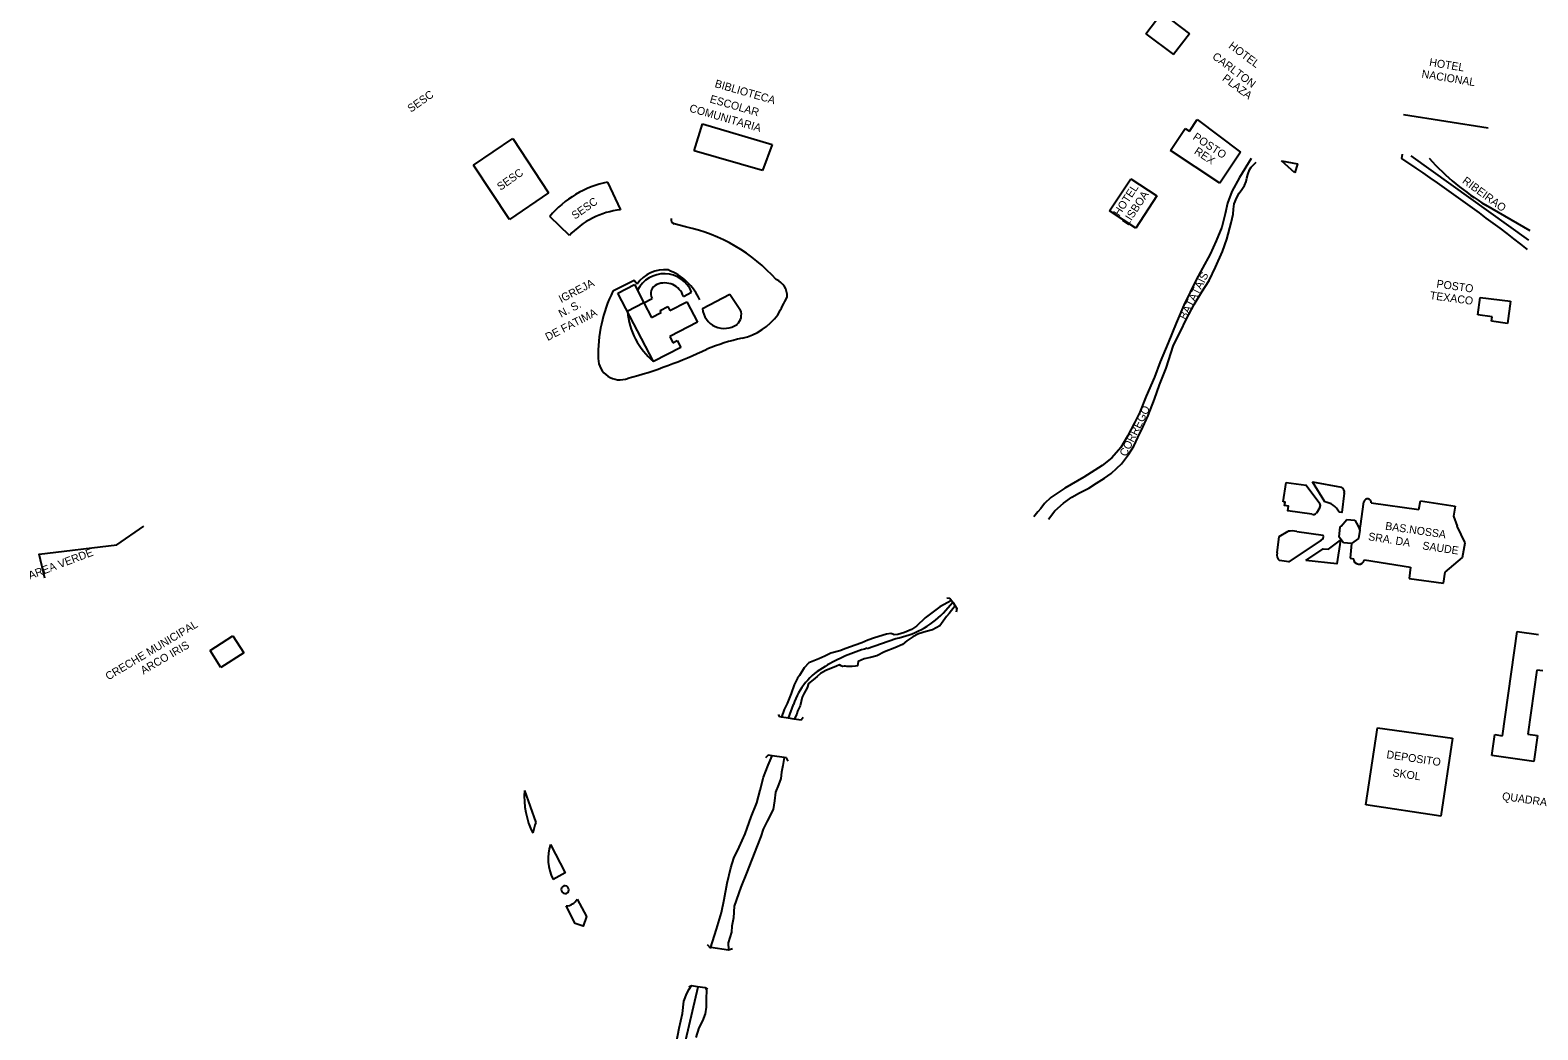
# Model space of a CAD drawing. Extents: x 325899 to 363134, y 7578590 to 7592502.
# Drawn here: x 337530 to 338292, y 7589247 to 7589753 of the extents above; entities that cross this region are included whole.
import ezdxf

# ---------------------------------------------------------------- set-up
doc = ezdxf.new("R2010")
doc.units = 0
for name, color, linetype in [('EDIFEXISTENT', 7, 'Continuous'), ('EDIFIDENTIF', 7, 'Continuous'), ('EDIFOBRAEXIS', 7, 'Continuous')]:
    doc.layers.add(name, color=color, linetype=linetype)

msp = doc.modelspace()

# ---------------------------------------------------------------- linework, layer by layer
at = {"layer": 'EDIFEXISTENT'}
for p, q in [((338093.53, 7589750.59), (338101.54, 7589761.3)), ((338101.54, 7589761.3), (338115.64, 7589750.75)), ((338093.53, 7589750.59), (338107.46, 7589740.16)), ((338115.64, 7589750.75), (338107.46, 7589740.16)), ((337865.22, 7589691.61), (337869.48, 7589705.19)), ((337869.48, 7589705.19), (337904.68, 7589694.73)), ((338105.97, 7589691.77), (338113.33, 7589702.92)), ((338113.33, 7589702.92), (338115.51, 7589701.48)), ((338115.51, 7589701.48), (338119.4, 7589707.4)), ((338119.4, 7589707.4), (338141.3, 7589690.91)), ((338223.69, 7589709.95), (338266.52, 7589703.2)), ((337753.58, 7589684.27), (337773.5, 7589697.83)), ((337773.5, 7589697.83), (337791.63, 7589670.29)), ((337899.77, 7589681.63), (337865.22, 7589691.61)), ((337904.68, 7589694.73), (337899.77, 7589681.63)), ((338130.96, 7589675.27), (338105.97, 7589691.77)), ((338141.3, 7589690.91), (338130.96, 7589675.27)), ((337771.86, 7589656.78), (337753.58, 7589684.27)), ((337821.38, 7589675.69), (337828.01, 7589661.75)), ((338075.18, 7589661.24), (338085.91, 7589677.48)), ((338085.91, 7589677.48), (338099.14, 7589668.74)), ((337791.63, 7589670.29), (337771.86, 7589656.78)), ((338099.14, 7589668.74), (338088.41, 7589652.48)), ((337802.14, 7589648.71), (337792.16, 7589658.35)), ((338088.41, 7589652.48), (338075.18, 7589661.24)), ((337826.65, 7589619.68), (337834.98, 7589624.01)), ((337844.63, 7589585.05), (337826.65, 7589619.68)), ((337834.98, 7589624.01), (337839.78, 7589614.76)), ((337859.74, 7589618.02), (337863.92, 7589620.19)), ((337839.78, 7589614.76), (337831.4, 7589610.41)), ((337839.78, 7589614.76), (337843.97, 7589616.93)), ((337839.78, 7589614.76), (337843.6, 7589607.39)), ((337847.94, 7589610.89), (337851.92, 7589612.96)), ((337851.92, 7589612.96), (337852.96, 7589610.95)), ((337852.96, 7589610.95), (337861.4, 7589615.33)), ((337861.4, 7589615.33), (337866.79, 7589604.93)), ((338261.32, 7589608.77), (338262.58, 7589617.5)), ((338262.58, 7589617.5), (338277.81, 7589615.53)), ((338277.81, 7589615.53), (338276.29, 7589604.36)), ((337843.6, 7589607.39), (337848.45, 7589609.91)), ((337848.45, 7589609.91), (337847.94, 7589610.89)), ((337866.79, 7589604.93), (337852.81, 7589597.68)), ((338268.55, 7589607.71), (338261.32, 7589608.77)), ((338268.2, 7589605.42), (338268.55, 7589607.71)), ((338276.29, 7589604.36), (338268.2, 7589605.42)), ((337852.81, 7589597.68), (337854.46, 7589594.51)), ((337858.46, 7589592.17), (337844.63, 7589585.05)), ((337854.46, 7589594.51), (337856.65, 7589595.65)), ((337856.65, 7589595.65), (337858.46, 7589592.17)), ((338202.06, 7589501.91), (338203.77, 7589514.19)), ((338207.48, 7589513.69), (338231.55, 7589510.41)), ((338231.55, 7589510.41), (338232.29, 7589514.74)), ((338232.29, 7589514.74), (338249.9, 7589512)), ((338249.9, 7589512), (338249.05, 7589507.02)), ((338192.22, 7589501.91), (338195.19, 7589505.25)), ((338195.19, 7589505.25), (338199.08, 7589504.94)), ((338199.08, 7589504.94), (338200.78, 7589501.91)), ((338249.05, 7589507.02), (338250.95, 7589501.91)), ((338191.18, 7589496.4), (338191.81, 7589501.57)), ((338191.81, 7589501.57), (338192.22, 7589501.91)), ((338200.78, 7589501.91), (338201.7, 7589499.84)), ((338201.7, 7589499.84), (338200.96, 7589495.74)), ((338201.7, 7589499.84), (338202.06, 7589501.91)), ((338254.87, 7589493.5), (338250.95, 7589501.91)), ((338193.38, 7589493.5), (338191.18, 7589496.4)), ((338197.46, 7589493.16), (338193.38, 7589493.5)), ((338197.46, 7589493.16), (338196.77, 7589485.81)), ((338200.96, 7589495.74), (338197.46, 7589493.16)), ((338253.54, 7589486.01), (338254.87, 7589493.5)), ((338196.77, 7589485.81), (338198.49, 7589485.46)), ((338203.99, 7589484.83), (338227.31, 7589481.19)), ((338244.86, 7589478.68), (338253.54, 7589486.01)), ((338227.31, 7589481.19), (338226.67, 7589475.44)), ((338226.67, 7589475.44), (338243.95, 7589473.06)), ((338243.95, 7589473.06), (338244.86, 7589478.68)), ((337992.92, 7589465.74), (337994.44, 7589465.6)), ((337994.44, 7589465.6), (337995.31, 7589464.32)), ((337995.31, 7589464.32), (337995.88, 7589463.48)), ((337995.88, 7589463.48), (337997.09, 7589461.71)), ((337997.09, 7589461.71), (337998.02, 7589460.35)), ((337998.02, 7589460.35), (337997.57, 7589458.45)), ((337620.49, 7589439.11), (337631.95, 7589446.45)), ((337631.95, 7589446.45), (337637.48, 7589437.98)), ((338273.74, 7589396.03), (338281.22, 7589448.72)), ((338281.22, 7589448.72), (338292.01, 7589447.19)), ((337625.91, 7589430.44), (337620.49, 7589439.11)), ((337637.48, 7589437.98), (337625.91, 7589430.44)), ((338291.22, 7589429.21), (338286.62, 7589396.85)), ((338294.24, 7589428.78), (338291.22, 7589429.21)), ((337908.46, 7589405.55), (337907.75, 7589406.8)), ((337909.31, 7589405.42), (337908.46, 7589405.55)), ((337912.85, 7589404.89), (337909.31, 7589405.42)), ((337915.76, 7589404.46), (337912.85, 7589404.89)), ((337919.22, 7589403.94), (337915.76, 7589404.46)), ((337920.34, 7589405.15), (337919.22, 7589403.94)), ((338204.77, 7589361.02), (338210.56, 7589400.04)), ((338210.56, 7589400.04), (338248.45, 7589394.82)), ((338248.45, 7589394.82), (338242.6, 7589355.41)), ((338268.41, 7589386.08), (338269.9, 7589396.57)), ((338269.9, 7589396.57), (338273.74, 7589396.03)), ((338286.62, 7589396.85), (338291.55, 7589396.15)), ((338291.55, 7589396.15), (338289.69, 7589383.06)), ((337902.54, 7589386.21), (337901.18, 7589384.93)), ((337904.64, 7589385.88), (337902.54, 7589386.21)), ((337910.6, 7589384.97), (337904.64, 7589385.88)), ((337911.8, 7589384.79), (337910.6, 7589384.97)), ((337912.73, 7589383.23), (337911.8, 7589384.79)), ((338289.69, 7589383.06), (338268.41, 7589386.08)), ((338242.6, 7589355.41), (338204.77, 7589361.02)), ((337871.8, 7589290.58), (337873.48, 7589288.61)), ((337873.48, 7589288.61), (337873.56, 7589289.19)), ((337873.56, 7589289.19), (337882.59, 7589287.87)), ((337882.59, 7589287.87), (337884.59, 7589288.54)), ((337862.51, 7589269.18), (337863.79, 7589269.85)), ((337863.79, 7589269.85), (337866.83, 7589269.35)), ((337866.83, 7589269.35), (337870.78, 7589268.81)), ((337870.78, 7589268.81), (337871.88, 7589267.93))]:
    msp.add_line(p, q, dxfattribs=at)
for centre, radius, start, end in [((337831.24, 7589625.78), 50.87, 101.1753, 140.19577), ((337832.18, 7589621.28), 40.68, 95.88187, 137.60579), ((337849.99, 7589614.35), 15.09, 22.73511, 152.90651), ((337848.02, 7589619.5), 4.79, 110.21393, 212.35293), ((337850.32, 7589614.89), 9.93, 18.37494, 113.51914), ((338205.61, 7589513.82), 1.88, 356.15001, 168.63769), ((338201.27, 7589485.46), 2.78, 179.8605, 347.06276)]:
    msp.add_arc(centre, radius, start, end, dxfattribs=at)
at = {"layer": 'EDIFOBRAEXIS'}
for points in [[(338146.68, 7589687.63), (338140.82, 7589678.11), (338137.03, 7589671.01), (338134.8, 7589665.04), (338133.54, 7589659.72), (338131.88, 7589653.01), (338129.04, 7589646.04), (338126.03, 7589639.38), (338122.18, 7589632.23), (338118.99, 7589626.32), (338112.74, 7589613.6), (338108.89, 7589604.47), (338104.77, 7589594.5), (338100.82, 7589584.94), (338097.81, 7589577.13), (338093.69, 7589567.64), (338090.55, 7589559.48), (338087.69, 7589554.18), (338084.25, 7589547.32), (338080.83, 7589541.62), (338076.39, 7589536.45), (338071.47, 7589532.58), (338062.2, 7589526.64), (338052.58, 7589521.03), (338045.42, 7589516.46), (338042.2, 7589513.38), (338040.38, 7589510.81), (338038.88, 7589509.08), (338036.83, 7589506.61)], [(338230.1, 7589682.84), (338222.94, 7589687.69), (338223.28, 7589689.81)], [(338287.12, 7589646.39), (338227.63, 7589689.08)], [(338044.3, 7589505.45), (338047.52, 7589509.71), (338051.88, 7589513.48), (338056.15, 7589516.51), (338060.01, 7589518.68), (338064.68, 7589521.15), (338068.51, 7589523.7), (338072.6, 7589526.15), (338076.02, 7589528.57), (338078.89, 7589531.17), (338081.25, 7589533.46), (338084.72, 7589538.04), (338087.46, 7589542.34), (338089.38, 7589546.69), (338091.94, 7589551.98), (338094.6, 7589557.83), (338097.94, 7589566.07), (338100.34, 7589573.37), (338103.78, 7589581.77), (338107.47, 7589593.34), (338111.04, 7589600.26), (338113.9, 7589606.39), (338117.9, 7589613.89), (338121.82, 7589620.26), (338125.45, 7589625.96), (338128.69, 7589632.8), (338132.26, 7589640.66), (338134.45, 7589646.97), (338136.57, 7589655.18), (338137.61, 7589659.48), (338137.78, 7589662.15), (338138.21, 7589664.74), (338139.42, 7589668.02), (338140.66, 7589670.21), (338141.95, 7589672.07), (338143.37, 7589674.05), (338144.16, 7589676.04), (338144.54, 7589677.76), (338144.99, 7589679.65), (338145.9, 7589681.96), (338146.76, 7589683.36), (338149.32, 7589685.88)], [(338162.09, 7589686.45), (338170.21, 7589684.98), (338168.77, 7589680.42)], [(338168.77, 7589680.42), (338162.09, 7589686.45)], [(338287.74, 7589651.18), (338265.42, 7589664.14)], [(337860.89, 7589653.12), (337855.01, 7589654.71)], [(337836.34, 7589624.22), (337834.89, 7589626.07), (337824.09, 7589620.61)], [(337869.39, 7589611.91), (337883.17, 7589619.21)], [(337883.17, 7589619.21), (337888.63, 7589611.08)], [(338162.86, 7589514.2), (338164.46, 7589523.94)], [(338164.46, 7589523.94), (338174.53, 7589522.7), (338181.47, 7589513.42)], [(338183.94, 7589514.12), (338177.73, 7589524.24)], [(338177.73, 7589524.24), (338192.46, 7589521.57)], [(338177.43, 7589508.02), (338165.27, 7589509.73), (338165.59, 7589511.97), (338163.68, 7589512.4), (338163.9, 7589514.05), (338162.86, 7589514.2)], [(338193.76, 7589518.5), (338192.55, 7589508.86), (338191.15, 7589509.01)], [(338181.38, 7589511.31), (338179.74, 7589508.43)], [(337536.87, 7589475.67), (337534.16, 7589487.82), (337573.38, 7589492.49), (337587.02, 7589501.91)], [(338159.87, 7589488.41), (338160.93, 7589496.64)], [(338160.93, 7589496.64), (338165.39, 7589499.36)], [(338169.78, 7589499.27), (338183.17, 7589497.31)], [(338182.19, 7589494.86), (338165.74, 7589483.89), (338161.11, 7589484.52)], [(338174.32, 7589484.5), (338183.14, 7589490.46), (338185.9, 7589490.31), (338191.85, 7589494.75), (338190.07, 7589482.8), (338174.32, 7589484.5)], [(337995.31, 7589464.32), (337989.35, 7589461.18), (337981.98, 7589455.54), (337977.63, 7589451.44), (337975.06, 7589449.64), (337971.44, 7589448.2), (337968.19, 7589447.24), (337966.21, 7589447.03), (337965.68, 7589447.41), (337964.54, 7589447.75), (337962.33, 7589447.36), (337956.33, 7589445.49), (337952.9, 7589444.35), (337949.9, 7589442.96), (337946.57, 7589441.79), (337941.81, 7589440.16), (337938.76, 7589438.97), (337934.23, 7589437.66), (337931.26, 7589436.24), (337928.13, 7589434.95), (337923.14, 7589432.92), (337920.83, 7589430.25), (337918.49, 7589426.39), (337917.37, 7589425.18), (337915.82, 7589421.67), (337914.26, 7589417.3), (337912.16, 7589412.22), (337910.74, 7589409.26), (337909.31, 7589405.42)], [(337997.09, 7589461.71), (337994.07, 7589457.74), (337992.79, 7589456.21), (337991.07, 7589453.89), (337989.4, 7589451.62), (337985.68, 7589449.5), (337982.53, 7589448.61), (337978.61, 7589447.56), (337975.66, 7589445.98), (337972.65, 7589443.98), (337970.45, 7589442.05), (337966.61, 7589440.38), (337961.45, 7589438.42), (337957.5, 7589436.35), (337954.4, 7589435.59), (337951.17, 7589434.83), (337948.17, 7589433.49), (337947.69, 7589431.36), (337946.7, 7589431.09), (337945.08, 7589431.03), (337943.61, 7589431.04), (337942.29, 7589431), (337941.61, 7589431.21), (337941.05, 7589431.09), (337940.13, 7589430.92), (337939.53, 7589431.31), (337938.7, 7589431.85), (337937.2, 7589431.1), (337931.8, 7589429.04), (337929.13, 7589427.44), (337927.36, 7589425.86), (337925.27, 7589424.23), (337923, 7589422.37), (337922.27, 7589420.25), (337920.8, 7589417.6), (337919.77, 7589415.58), (337918.77, 7589411.15), (337917.38, 7589408.47), (337917.16, 7589406.93), (337915.76, 7589404.46)], [(337991.05, 7589457.9), (337995.88, 7589463.48)], [(337952.61, 7589440.17), (337967.13, 7589445.22)], [(337912.85, 7589404.89), (337915.35, 7589411.84)], [(337873.48, 7589288.61), (337876.48, 7589298.22), (337879.06, 7589306.62), (337880.33, 7589313.25), (337881.95, 7589321.55), (337883.72, 7589329.35), (337885.25, 7589334.15), (337887.99, 7589339.76), (337890.91, 7589346.5), (337894.05, 7589355.07), (337896.85, 7589362.12), (337898.55, 7589368.49), (337900.31, 7589375.1), (337902.67, 7589381.06), (337904.64, 7589385.88)], [(337910.6, 7589384.97), (337910.04, 7589381.05), (337909.33, 7589377.63), (337908.95, 7589374.47), (337907.8, 7589371.18), (337906.3, 7589367.47), (337905.73, 7589363.16), (337905.06, 7589358.73), (337902.02, 7589352.82), (337900.13, 7589348.73), (337898.83, 7589345.09), (337897.04, 7589340.34), (337894.32, 7589333.44), (337891.63, 7589326.51), (337888.86, 7589319.49), (337885.48, 7589309.86), (337885, 7589304.01), (337884.22, 7589299.75), (337884.05, 7589296.84), (337882.43, 7589291.32), (337882.59, 7589287.87)], [(337779.41, 7589368.32), (337785.18, 7589352.17)], [(337792.54, 7589341.13), (337800.05, 7589326.66), (337793.83, 7589323.44)], [(337805.99, 7589313.45), (337810.74, 7589304.64), (337809.12, 7589299.71), (337805.08, 7589301.19), (337800.44, 7589310.05)], [(337855.25, 7589217.7), (337867.2, 7589269.19)], [(337856.34, 7589241.14), (337857.54, 7589248.25), (337859.31, 7589255.74), (337859.97, 7589261.82), (337861.5, 7589265.74), (337862.58, 7589267.99), (337863.79, 7589269.85)], [(337870.78, 7589268.81), (337871.45, 7589267.43), (337871.28, 7589263), (337871.25, 7589258.91), (337870.79, 7589255.42), (337869.34, 7589251.91), (337867.53, 7589248.37), (337865.97, 7589243.54)]]:
    msp.add_lwpolyline(points, dxfattribs=at)
for centre, radius, start, end in [((338328.64, 7589770.03), 123.32, 221.83857, 239.15933), ((337642.07, 7588816.75), 1046.84, 52.01007, 55.82538), ((337856, 7589657.06), 2.54, 171.20271, 247.0167), ((337842.87, 7589569.44), 85.6, 41.77599, 77.84914), ((337850.09, 7589614.83), 16.65, 83.49553, 145.64804), ((337841.97, 7589604.66), 28.51, 23.98904, 69.46606), ((337903.29, 7589618.24), 8.91, 357.03775, 67.45919), ((337889.76, 7589588.41), 73.14, 153.87874, 181.45763), ((337880.43, 7589612.91), 11.09, 185.18911, 305.49387), ((337882.53, 7589608.77), 6.52, 311.62031, 20.8159), ((337775.16, 7589683.17), 151.83, 330.64635, 334.48869), ((337868.86, 7589613.82), 37.61, 185.1982, 229.89694), ((337882.25, 7589627.45), 31.42, 283.26888, 323.47344), ((337913.15, 7589487.48), 111.92, 102.22039, 111.8395), ((337770.87, 7589801.87), 233.32, 285.1026, 295.55293), ((337827.64, 7589586.84), 11, 181.52177, 291.46305), ((338191.27, 7589519.25), 2.6, 343.15101, 62.9467), ((338179.8, 7589512.44), 1.94, 324.48771, 30.38214), ((338183.06, 7589505.23), 8.93, 25.01972, 84.33131), ((338178.27, 7589509.97), 2.12, 246.55552, 313.77667), ((338167.28, 7589484.3), 15.18, 80.54111, 97.15793), ((338181.37, 7589496.61), 1.93, 294.99688, 21.24107), ((338163.1, 7589487.29), 3.41, 160.8994, 234.31885), ((337958.86, 7589489.72), 45.27, 280.52844, 315.32216), ((337976.17, 7589356.47), 86.96, 105.71723, 120.97596), ((337947.48, 7589401.25), 33.82, 118.3569, 161.76937), ((337822.33, 7589365.45), 43.01, 176.17317, 205.7558), ((337826.36, 7589337.11), 43.85, 159.91335, 167.29032), ((337814.53, 7589333.85), 23.17, 161.68783, 206.68628), ((337799.99, 7589318.26), 2.02, 110.64796, 287.97352), ((337799.84, 7589318.2), 2.02, 292.69804, 105.92344), ((337800.29, 7589316.54), 6.49, 271.33589, 331.60406)]:
    msp.add_arc(centre, radius, start, end, dxfattribs=at)

# ---------------------------------------------------------------- texts
at = {"layer": 'EDIFIDENTIF'}
for s, rotation, p in [(' CARLTON', 323.19648, (338125.56, 7589739.36)), ('HOTEL', 323.19648, (338134.98, 7589743.9)), ('HOTEL', 350.63007, (338236.56, 7589734.51)), ('BIBLIOTECA', 343.90458, (337875.29, 7589723.83)), ('PLAZA', 323.19648, (338131.78, 7589727.44)), ('NACIONAL', 350.63007, (338232.7, 7589728.65)), ('SESC', 34.9809, (337722, 7589710.78)), ('ESCOLAR', 343.90458, (337872.77, 7589716.05)), ('COMUNITARIA', 343.90458, (337862.43, 7589711.43)), ('POSTO', 326.55841, (338116.92, 7589697.68)), ('REX', 326.55841, (338117.6, 7589690.44)), ('SESC', 34.9809, (337767.28, 7589671.31)), ('HOTEL', 56.55841, (338080.13, 7589658.18)), ('RIBEIRAO', 323.82086, (338253.12, 7589675.61)), ('SESC', 34.9809, (337804.92, 7589656.72)), ('LISBOA', 56.55841, (338084.5, 7589653.48)), ('IGREJA', 27.43492, (337797.97, 7589614.6)), ('BATATAIS', 63.295, (338113.7, 7589605.87)), ('POSTO', 351.98607, (338240.25, 7589622.51)), ('TEXACO', 352.34577, (338236.88, 7589616.65)), ('DE FATIMA', 27.43492, (337791.19, 7589595.43)), ('N. S.', 27.43492, (337797.91, 7589607.21)), ('CORREGO', 63.66931, (338083.56, 7589536.76)), ('SRA. DA', 351.13514, (338205.7, 7589494.85)), ('BAS.NOSSA', 351.65411, (338214.32, 7589500.17)), ('AREA VERDE', 20.73601, (337529.53, 7589474.94)), ('SAUDE', 351.60905, (338233.12, 7589490.23)), ('CRECHE MUNICIPAL', 30.90888, (337569.09, 7589423.88)), ('ARCO IRIS', 30.28818, (337586.8, 7589426.91)), ('DEPOSITO', 351.56056, (338214.96, 7589384.71)), ('SKOL', 351.56056, (338217.99, 7589375.55)), ('QUADRA', 351.91946, (338273.41, 7589363.62))]:
    msp.add_text(s, height=4, rotation=rotation, dxfattribs=at).set_placement(p)

doc.saveas('drawing.dxf')
